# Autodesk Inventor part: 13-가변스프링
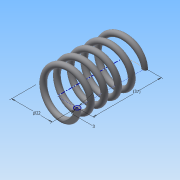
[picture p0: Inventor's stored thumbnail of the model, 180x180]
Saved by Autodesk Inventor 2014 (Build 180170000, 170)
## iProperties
Created: 2015-09
Part Number: 13-가변스프링
Material: 강철, 탄소
Document SubType Name: Modeling
Designer: study
Density: 7.87 g/cm^3
Appearance: 반연마
Mass: 18.8544 g
Surface Area: 32.5077 cm^2
Volume: 2.39574 cm^3
Author: study
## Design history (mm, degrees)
sketch "스케치1"
  geometry: L1 (0, 0)-(11, 0); L2 (11, 0)-(11, 39.945); L3 (11, 39.945)-(0, 39.945); L4 (0, 39.945)-(0, 0); C1 r 1.5 at (11, 0)
  constraints: 8 end point, 2 parallel, 1 centre point, 1 coincident, 1 horizontal, 1 perpendicular
  dimensions: "d0" = 3 diameter of C1; "d1" = 22 diameter of L2 L4; "d2" = 39.9455 distance of L1.end L2.end (derived)
feature "코일1" pitch "d3" = 10; turns "d5" = 5; dims "d4" = 39.9455 (= d2), "d6" = 0, angle "d7" = 90 deg, angle "d8" = 90 deg, "d9" = 0, "d10" = 0
node "작업 평면1"
sketch "스케치2"
  geometry: L1 (-12.5, 0)-(-9.5, 0) reference; L2 (-12.5, 0)-(-9.5, 0) reference; 1 further point
  constraints: 2 horizontal alignment
extrude "돌출1" cut sketch "스케치2" stored distance "d12" = 10; taper "d13" = 0 deg
node "작업 평면2"
sketch "스케치3"
  geometry: L1 (-9.5, 0)-(-12.5, 0) reference; 1 further point
  constraints: 1 horizontal alignment
extrude "돌출2" cut sketch "스케치3" stored distance "d15" = 10; taper "d16" = 0 deg
node "솔리드1"
node "절단 모서리 투영1"
node "절단 모서리 투영2"
node "절단 모서리 투영3"
other parameters: "d11" = 0, "d14" = 39.9455 (= d2)
